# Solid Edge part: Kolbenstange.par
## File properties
Username: bmolnar
Dokumentum tartalom típus: 0
Author: bmolnar
Last saved by: bmolnar
Revision: 83
Sűrűség: 0,000 kg/m^3
Pontosság: 0,990
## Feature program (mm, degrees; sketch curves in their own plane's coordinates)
base feature "unnamed BaseFeature 1"
sketch for "unnamed Protrusion 1" plane through (0, 0.0012, 0) normal (-1, 0, 0) x-axis (0, -1, 0)
  circle centre (0.0012, 0) radius 40
extrude "unnamed Protrusion 1" add finite 9.15 along +normal
sketch for "Furat_1" plane through (93.5, 0, 0) normal (1, 0, 0) x-axis (0, 1, 0)
  hole centre (0, 0) bore radius 4.188
hole "Furat_1" nominal diameter 10 finite  VBottomAngle = 118 deg; ThreadDepth = 13.5 mm
chamfer "Letörés_1" setback 0.8  SetBackValue2 = 45 deg
sketch for "Kihúzás_3" #1 plane through (0, 0.0012, 0) normal (-1, 0, 0) x-axis (0, -1, 0)
  circle centre (0.0012, 0) radius 10
sketch for "Kihúzás_3" #2 plane through (0, 0.0012, 0) normal (-1, 0, 0) x-axis (0, -1, 0)
  circle centre (0.0012, 0) radius 40
extrude "Kihúzás_3" add finite 31.15 along -normal
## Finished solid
Body 1: solid body, 17 faces, 23 edges, 8 vertices.
  Faces by surface: plane 7, cylinder 5, cone 3, torus 2
  Edges by curve: circle 13, line 6, curve on surface 2, ellipse 2
Bounding box of the edges (mm; curved faces can reach further): 106.150 x 80.000 x 80.000, from (-9.15, -40, -40) to (97, 40, 40).
Cylindrical faces by radius (mm): R4.188 x2, R5.125 x1, R10 x1, R40 x1
Conical faces (half-angle, radius in mm at the cone's reference point): 45 deg R4.988 x1, 45 deg R5.225 x1, 59 deg R4.188 x1
Toroidal faces (ring radius, tube radius in mm): R4.925 r0.2 x1, R8.2 r1.8 x1
Planar faces by outward normal: +x 2, +z 1, -x 1, -z 1, oblique 2
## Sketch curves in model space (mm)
circle centre (0, 0, 0) radius 10
circle centre (0, 0, 0) radius 40
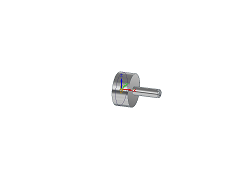
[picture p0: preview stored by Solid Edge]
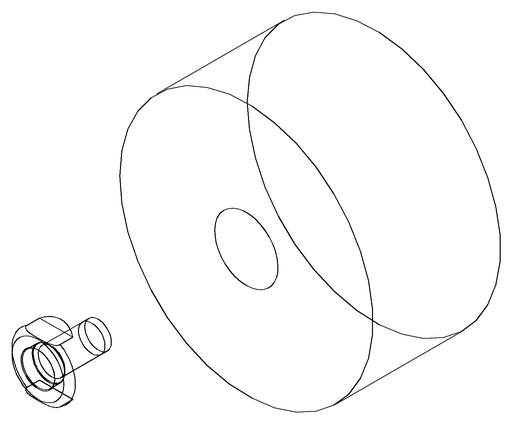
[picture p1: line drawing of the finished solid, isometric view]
